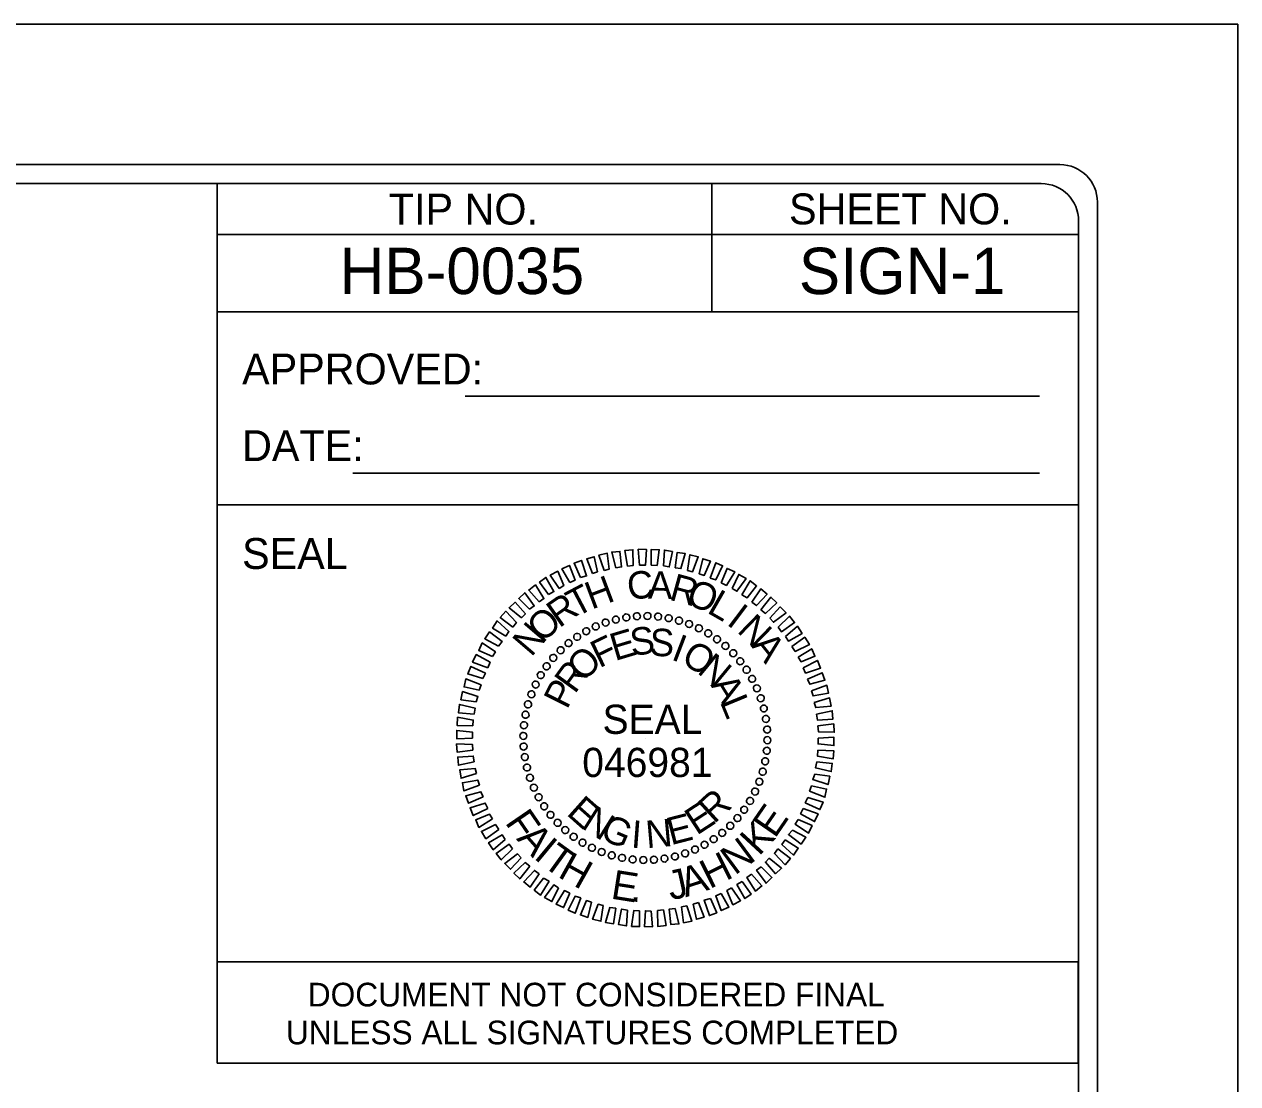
# Model space of a CAD drawing. Extents: x 1359317 to 1361345, y 1001522 to 1002524.
# Drawn here: x 1360569.7 to 1360865, y 1002265.9 to 1002523.7 of the extents above; entities that cross this region are included whole.
import ezdxf

# ---------------------------------------------------------------- set-up
doc = ezdxf.new("R2010")
doc.units = 0
for name, color, linetype in [('Sheet Data Field CELL', 7, 'Continuous'), ('Sheet PE Seal CELL', 7, 'Continuous'), ('Sheet Plot Border Outside CELL', 7, 'Continuous'), ('Sheet Title CELL', 7, 'Continuous'), ('Sheet_Title_CELL', 7, 'Continuous'), ('z - Construction', 7, 'Continuous')]:
    doc.layers.add(name, color=color, linetype=linetype)

msp = doc.modelspace()

# ---------------------------------------------------------------- linework, layer by layer
at = {"layer": 'Sheet PE Seal CELL'}
for p, q in [((1360708.79, 1002377.21), (1360708.79, 1002377.21)), ((1360711.16, 1002378.16), (1360711.16, 1002378.16)), ((1360713.64, 1002378.87), (1360713.64, 1002378.87)), ((1360716.25, 1002379.34), (1360716.25, 1002379.34)), ((1360718.79, 1002379.7), (1360718.79, 1002379.7)), ((1360721.4, 1002379.76), (1360721.4, 1002379.76)), ((1360724, 1002379.58), (1360724, 1002379.58)), ((1360726.55, 1002379.17), (1360726.55, 1002379.17)), ((1360729.04, 1002378.63), (1360729.04, 1002378.63)), ((1360731.52, 1002377.8), (1360731.52, 1002377.8)), ((1360704.23, 1002374.67), (1360704.23, 1002374.67)), ((1360706.48, 1002376.03), (1360706.48, 1002376.03)), ((1360733.89, 1002376.74), (1360733.89, 1002376.74)), ((1360736.2, 1002375.55), (1360736.2, 1002375.55)), ((1360700.2, 1002371.41), (1360700.2, 1002371.41)), ((1360702.15, 1002373.19), (1360702.15, 1002373.19)), ((1360738.33, 1002374.07), (1360738.33, 1002374.07)), ((1360740.41, 1002372.47), (1360740.41, 1002372.47)), ((1360698.42, 1002369.57), (1360698.42, 1002369.57)), ((1360742.24, 1002370.7), (1360742.24, 1002370.7)), ((1360744.02, 1002368.74), (1360744.02, 1002368.74)), ((1360696.83, 1002367.5), (1360696.83, 1002367.5)), ((1360745.5, 1002366.67), (1360745.5, 1002366.67)), ((1360694.16, 1002363.06), (1360694.16, 1002363.06)), ((1360695.34, 1002365.37), (1360695.34, 1002365.37)), ((1360746.86, 1002364.42), (1360746.86, 1002364.42)), ((1360693.09, 1002360.69), (1360693.09, 1002360.69)), ((1360748.05, 1002362.11), (1360748.05, 1002362.11)), ((1360748.99, 1002359.74), (1360748.99, 1002359.74)), ((1360692.27, 1002358.2), (1360692.27, 1002358.2)), ((1360749.7, 1002357.26), (1360749.7, 1002357.26)), ((1360691.73, 1002355.72), (1360691.73, 1002355.72)), ((1360750.18, 1002354.65), (1360750.18, 1002354.65)), ((1360691.32, 1002353.17), (1360691.32, 1002353.17)), ((1360750.53, 1002352.11), (1360750.53, 1002352.11)), ((1360691.14, 1002350.57), (1360691.14, 1002350.57)), ((1360691.2, 1002347.96), (1360691.2, 1002347.96)), ((1360720.87, 1002350.03), (1360720.87, 1002350.03)), ((1360750.59, 1002349.5), (1360750.59, 1002349.5)), ((1360691.56, 1002345.41), (1360691.56, 1002345.41)), ((1360750.41, 1002346.89), (1360750.41, 1002346.89)), ((1360692.03, 1002342.81), (1360692.03, 1002342.81)), ((1360749.47, 1002341.86), (1360749.47, 1002341.86)), ((1360750, 1002344.35), (1360750, 1002344.35)), ((1360692.74, 1002340.32), (1360692.74, 1002340.32)), ((1360748.64, 1002339.37), (1360748.64, 1002339.37)), ((1360693.69, 1002337.95), (1360693.69, 1002337.95)), ((1360747.57, 1002337.01), (1360747.57, 1002337.01)), ((1360694.87, 1002335.64), (1360694.87, 1002335.64)), ((1360696.23, 1002333.39), (1360696.23, 1002333.39)), ((1360746.39, 1002334.7), (1360746.39, 1002334.7)), ((1360697.71, 1002331.32), (1360697.71, 1002331.32)), ((1360743.31, 1002330.49), (1360743.31, 1002330.49)), ((1360744.91, 1002332.56), (1360744.91, 1002332.56)), ((1360699.49, 1002329.37), (1360699.49, 1002329.37)), ((1360701.33, 1002327.59), (1360701.33, 1002327.59)), ((1360741.53, 1002328.66), (1360741.53, 1002328.66)), ((1360703.4, 1002325.99), (1360703.4, 1002325.99)), ((1360705.53, 1002324.51), (1360705.53, 1002324.51)), ((1360737.51, 1002325.4), (1360737.51, 1002325.4)), ((1360739.58, 1002326.88), (1360739.58, 1002326.88)), ((1360707.84, 1002323.33), (1360707.84, 1002323.33)), ((1360710.21, 1002322.26), (1360710.21, 1002322.26)), ((1360712.69, 1002321.43), (1360712.69, 1002321.43)), ((1360728.09, 1002321.2), (1360728.09, 1002321.2)), ((1360730.58, 1002321.91), (1360730.58, 1002321.91)), ((1360732.95, 1002322.85), (1360732.95, 1002322.85)), ((1360735.26, 1002324.04), (1360735.26, 1002324.04)), ((1360715.18, 1002320.9), (1360715.18, 1002320.9)), ((1360717.73, 1002320.48), (1360717.73, 1002320.48)), ((1360720.33, 1002320.31), (1360720.33, 1002320.31)), ((1360722.94, 1002320.37), (1360722.94, 1002320.37)), ((1360725.48, 1002320.72), (1360725.48, 1002320.72))]:
    msp.add_line(p, q, dxfattribs=at)
for points in [[(1360710.8, 1002390.83), (1360709.56, 1002394.56), (1360711.57, 1002394.98), (1360712.04, 1002391.13)], [(1360713.64, 1002391.48), (1360712.69, 1002395.27), (1360714.65, 1002395.45), (1360715.06, 1002391.66)], [(1360716.48, 1002391.84), (1360715.83, 1002395.63), (1360717.85, 1002395.86), (1360717.91, 1002392.02)], [(1360719.44, 1002392.13), (1360719.15, 1002395.98), (1360721.1, 1002395.92), (1360720.87, 1002392.07)], [(1360722.29, 1002392.07), (1360722.29, 1002395.92), (1360724.24, 1002395.86), (1360723.71, 1002392.02)], [(1360725.25, 1002391.9), (1360725.48, 1002395.75), (1360727.44, 1002395.39), (1360726.67, 1002391.66)], [(1360728.09, 1002391.42), (1360728.62, 1002395.21), (1360730.58, 1002394.92), (1360729.51, 1002391.25)], [(1360702.45, 1002387.87), (1360700.56, 1002391.19), (1360702.39, 1002392.02), (1360703.75, 1002388.4)], [(1360705.06, 1002389.11), (1360703.52, 1002392.55), (1360705.29, 1002393.26), (1360706.54, 1002389.47)], [(1360707.96, 1002390.06), (1360706.6, 1002393.61), (1360708.43, 1002394.15), (1360709.2, 1002390.48)], [(1360731.11, 1002390.77), (1360731.7, 1002394.62), (1360733.72, 1002394.15), (1360732.35, 1002390.48)], [(1360733.95, 1002390), (1360734.84, 1002393.67), (1360736.68, 1002393.08), (1360735.2, 1002389.59)], [(1360736.62, 1002388.94), (1360737.98, 1002392.67), (1360739.64, 1002391.96), (1360737.98, 1002388.52)], [(1360697.3, 1002384.97), (1360695.11, 1002387.99), (1360696.65, 1002389.11), (1360698.6, 1002385.68)], [(1360699.9, 1002386.45), (1360697.71, 1002389.65), (1360699.55, 1002390.59), (1360701.03, 1002387.16)], [(1360739.28, 1002387.81), (1360740.76, 1002391.31), (1360742.6, 1002390.48), (1360740.58, 1002387.16)], [(1360742.01, 1002386.45), (1360743.6, 1002389.82), (1360745.38, 1002388.82), (1360743.13, 1002385.74)], [(1360695.05, 1002383.19), (1360692.5, 1002386.04), (1360694.1, 1002387.28), (1360696.17, 1002383.96)], [(1360744.31, 1002384.85), (1360746.39, 1002388.29), (1360747.93, 1002387.04), (1360745.62, 1002384.14)], [(1360746.74, 1002383.07), (1360748.93, 1002386.33), (1360750.47, 1002385.03), (1360747.87, 1002382.25)], [(1360692.68, 1002381.36), (1360690.07, 1002383.96), (1360691.5, 1002385.38), (1360693.81, 1002382.19)], [(1360748.99, 1002381.24), (1360751.42, 1002384.32), (1360752.84, 1002382.9), (1360750.12, 1002380.35)], [(1360688.65, 1002377.03), (1360685.57, 1002379.34), (1360686.88, 1002380.88), (1360689.48, 1002378.1)], [(1360690.73, 1002379.28), (1360687.71, 1002381.71), (1360689.19, 1002383.07), (1360691.67, 1002380.23)], [(1360751.12, 1002379.17), (1360753.67, 1002381.95), (1360755.09, 1002380.53), (1360752.01, 1002378.22)], [(1360686.88, 1002374.78), (1360683.68, 1002376.8), (1360684.8, 1002378.51), (1360687.65, 1002375.91)], [(1360753.2, 1002377.03), (1360755.92, 1002379.7), (1360757.16, 1002378.1), (1360754.03, 1002375.85)], [(1360754.97, 1002374.73), (1360757.88, 1002377.21), (1360759, 1002375.49), (1360755.68, 1002373.6)], [(1360685.1, 1002372.42), (1360681.78, 1002374.19), (1360682.97, 1002375.85), (1360686.05, 1002373.48)], [(1360756.51, 1002372.3), (1360759.65, 1002374.55), (1360760.78, 1002372.77), (1360757.34, 1002371.11)], [(1360683.68, 1002369.87), (1360680.3, 1002371.35), (1360681.19, 1002373.19), (1360684.39, 1002370.99)], [(1360758.05, 1002369.69), (1360761.37, 1002371.76), (1360762.14, 1002369.93), (1360758.76, 1002368.57)], [(1360682.5, 1002367.15), (1360678.82, 1002368.51), (1360679.71, 1002370.34), (1360683.09, 1002368.45)], [(1360759.24, 1002367.15), (1360762.73, 1002368.92), (1360763.5, 1002367.03), (1360759.83, 1002365.84)], [(1360681.31, 1002364.54), (1360677.64, 1002365.61), (1360678.41, 1002367.44), (1360681.96, 1002365.78)], [(1360760.3, 1002364.36), (1360763.91, 1002365.9), (1360764.57, 1002364.07), (1360760.89, 1002363.12)], [(1360680.42, 1002361.7), (1360676.75, 1002362.47), (1360677.17, 1002364.42), (1360680.9, 1002362.94)], [(1360761.25, 1002361.52), (1360765.04, 1002362.88), (1360765.4, 1002360.93), (1360761.66, 1002360.28)], [(1360679.65, 1002358.86), (1360675.98, 1002359.33), (1360676.4, 1002361.34), (1360680.13, 1002360.1)], [(1360761.96, 1002358.68), (1360765.69, 1002359.8), (1360766.05, 1002357.79), (1360762.32, 1002357.43)], [(1360679.18, 1002355.84), (1360675.39, 1002356.19), (1360675.63, 1002358.2), (1360679.48, 1002357.26)], [(1360762.49, 1002355.84), (1360766.34, 1002356.66), (1360766.52, 1002354.65), (1360762.73, 1002354.41)], [(1360678.88, 1002352.99), (1360675.03, 1002353.11), (1360675.15, 1002355.07), (1360679, 1002354.41)], [(1360678.82, 1002350.03), (1360674.98, 1002349.86), (1360674.98, 1002351.87), (1360678.82, 1002351.45)], [(1360762.85, 1002352.99), (1360766.7, 1002353.47), (1360766.82, 1002351.45), (1360762.97, 1002351.57)], [(1360678.88, 1002347.07), (1360675.03, 1002346.6), (1360674.92, 1002348.61), (1360678.76, 1002348.49)], [(1360762.91, 1002350.03), (1360766.76, 1002350.21), (1360766.76, 1002348.2), (1360762.91, 1002348.61)], [(1360679.24, 1002344.23), (1360675.39, 1002343.4), (1360675.21, 1002345.41), (1360679, 1002345.65)], [(1360762.85, 1002347.07), (1360766.7, 1002346.95), (1360766.58, 1002345), (1360762.73, 1002345.65)], [(1360679.77, 1002341.39), (1360676.04, 1002340.26), (1360675.69, 1002342.28), (1360679.42, 1002342.63)], [(1360762.55, 1002344.23), (1360766.34, 1002343.87), (1360766.11, 1002341.86), (1360762.26, 1002342.81)], [(1360680.48, 1002338.55), (1360676.69, 1002337.18), (1360676.34, 1002339.14), (1360680.07, 1002339.79)], [(1360762.08, 1002341.21), (1360765.75, 1002340.74), (1360765.34, 1002338.72), (1360761.61, 1002339.97)], [(1360681.43, 1002335.7), (1360677.82, 1002334.16), (1360677.17, 1002336), (1360680.84, 1002336.95)], [(1360761.31, 1002338.37), (1360764.98, 1002337.6), (1360764.57, 1002335.64), (1360760.84, 1002337.12)], [(1360682.5, 1002332.92), (1360679, 1002331.14), (1360678.23, 1002333.04), (1360681.9, 1002334.22)], [(1360759.24, 1002332.92), (1360762.91, 1002331.56), (1360762.02, 1002329.72), (1360758.64, 1002331.62)], [(1360760.42, 1002335.53), (1360764.09, 1002334.46), (1360763.32, 1002332.62), (1360759.77, 1002334.28)], [(1360683.68, 1002330.37), (1360680.36, 1002328.3), (1360679.59, 1002330.14), (1360682.97, 1002331.5)], [(1360758.05, 1002330.2), (1360761.43, 1002328.72), (1360760.54, 1002326.88), (1360757.34, 1002329.07)], [(1360685.22, 1002327.77), (1360682.08, 1002325.52), (1360680.96, 1002327.29), (1360684.39, 1002328.95)], [(1360756.63, 1002327.65), (1360759.95, 1002325.87), (1360758.76, 1002324.22), (1360755.68, 1002326.58)], [(1360686.76, 1002325.34), (1360683.86, 1002322.85), (1360682.73, 1002324.57), (1360686.05, 1002326.47)], [(1360688.54, 1002323.03), (1360685.81, 1002320.37), (1360684.57, 1002321.97), (1360687.71, 1002324.22)], [(1360754.86, 1002325.28), (1360758.05, 1002323.27), (1360756.93, 1002321.55), (1360754.09, 1002324.16)], [(1360690.61, 1002320.9), (1360688.06, 1002318.12), (1360686.64, 1002319.54), (1360689.72, 1002321.85)], [(1360753.08, 1002323.03), (1360756.16, 1002320.72), (1360754.86, 1002319.18), (1360752.25, 1002321.97)], [(1360692.74, 1002318.83), (1360690.31, 1002315.75), (1360688.89, 1002317.17), (1360691.61, 1002319.72)], [(1360749.05, 1002318.71), (1360751.66, 1002316.1), (1360750.24, 1002314.68), (1360747.93, 1002317.88)], [(1360751.01, 1002320.78), (1360754.03, 1002318.35), (1360752.55, 1002316.99), (1360750.06, 1002319.83)], [(1360694.99, 1002316.99), (1360692.8, 1002313.73), (1360691.26, 1002315.04), (1360693.86, 1002317.82)], [(1360697.42, 1002315.21), (1360695.34, 1002311.78), (1360693.81, 1002313.02), (1360696.11, 1002315.93)], [(1360746.68, 1002316.87), (1360749.23, 1002314.03), (1360747.63, 1002312.79), (1360745.56, 1002316.1)], [(1360699.73, 1002313.62), (1360698.13, 1002310.24), (1360696.35, 1002311.25), (1360698.6, 1002314.33)], [(1360702.45, 1002312.25), (1360700.97, 1002308.76), (1360699.13, 1002309.59), (1360701.15, 1002312.91)], [(1360741.83, 1002313.62), (1360744.02, 1002310.42), (1360742.18, 1002309.47), (1360740.7, 1002312.91)], [(1360744.43, 1002315.1), (1360746.62, 1002312.08), (1360745.08, 1002310.95), (1360743.13, 1002314.39)], [(1360705.12, 1002311.13), (1360703.75, 1002307.4), (1360702.1, 1002308.11), (1360703.75, 1002311.54)], [(1360707.78, 1002310.06), (1360706.89, 1002306.39), (1360705.06, 1002306.98), (1360706.54, 1002310.48)], [(1360710.62, 1002309.29), (1360710.03, 1002305.44), (1360708.02, 1002305.92), (1360709.38, 1002309.59)], [(1360733.77, 1002310), (1360735.14, 1002306.45), (1360733.3, 1002305.92), (1360732.53, 1002309.59)], [(1360736.68, 1002310.95), (1360738.22, 1002307.52), (1360736.44, 1002306.81), (1360735.2, 1002310.6)], [(1360739.28, 1002312.19), (1360741.18, 1002308.88), (1360739.34, 1002308.05), (1360737.98, 1002311.66)], [(1360713.64, 1002308.64), (1360713.11, 1002304.85), (1360711.16, 1002305.15), (1360712.22, 1002308.82)], [(1360716.48, 1002308.17), (1360716.25, 1002304.32), (1360714.29, 1002304.67), (1360715.06, 1002308.41)], [(1360719.44, 1002307.99), (1360719.44, 1002304.14), (1360717.49, 1002304.2), (1360718.02, 1002308.05)], [(1360722.29, 1002307.93), (1360722.58, 1002304.08), (1360720.63, 1002304.14), (1360720.87, 1002307.99)], [(1360725.25, 1002308.23), (1360725.9, 1002304.44), (1360723.89, 1002304.2), (1360723.83, 1002308.05)], [(1360728.09, 1002308.58), (1360729.04, 1002304.79), (1360727.08, 1002304.62), (1360726.67, 1002308.41)], [(1360730.93, 1002309.23), (1360732.18, 1002305.5), (1360730.16, 1002305.09), (1360729.69, 1002308.94)]]:
    msp.add_lwpolyline(points, close=True, dxfattribs=at)
for centre, major_axis in [((1360716.22, 1002379.37), (-0.133, 0.842)), ((1360718.79, 1002379.66), (-0.059, 0.851)), ((1360721.38, 1002379.73), (0.015, 0.853)), ((1360723.97, 1002379.57), (0.089, 0.848)), ((1360708.79, 1002377.17), (-0.347, 0.779)), ((1360711.2, 1002378.12), (-0.278, 0.806)), ((1360713.68, 1002378.85), (-0.206, 0.827)), ((1360726.53, 1002379.19), (0.163, 0.837)), ((1360729.05, 1002378.58), (0.235, 0.82)), ((1360731.51, 1002377.76), (0.306, 0.796)), ((1360733.89, 1002376.73), (0.374, 0.766)), ((1360704.26, 1002374.66), (-0.477, 0.707)), ((1360706.47, 1002376.01), (-0.413, 0.746)), ((1360736.16, 1002375.49), (0.439, 0.731)), ((1360738.32, 1002374.06), (0.501, 0.69)), ((1360700.23, 1002371.4), (-0.592, 0.613)), ((1360702.17, 1002373.12), (-0.537, 0.663)), ((1360740.35, 1002372.45), (0.559, 0.644)), ((1360742.23, 1002370.67), (0.613, 0.592)), ((1360696.84, 1002367.49), (-0.69, 0.501)), ((1360698.45, 1002369.52), (-0.644, 0.559)), ((1360743.95, 1002368.72), (0.663, 0.537)), ((1360695.41, 1002365.33), (-0.731, 0.439)), ((1360745.49, 1002366.64), (0.707, 0.477)), ((1360746.84, 1002364.43), (0.746, 0.413)), ((1360694.17, 1002363.05), (-0.766, 0.374)), ((1360748, 1002362.11), (0.779, 0.347)), ((1360693.14, 1002360.68), (-0.796, 0.306)), ((1360748.95, 1002359.7), (0.806, 0.278)), ((1360691.71, 1002355.7), (-0.837, 0.163)), ((1360692.31, 1002358.22), (-0.82, 0.235)), ((1360749.69, 1002357.22), (0.827, 0.206)), ((1360691.33, 1002353.14), (-0.848, 0.089)), ((1360750.2, 1002354.68), (0.842, 0.133)), ((1360691.17, 1002350.55), (-0.853, 0.015)), ((1360750.5, 1002352.1), (0.851, 0.059)), ((1360691.24, 1002347.96), (-0.851, -0.059)), ((1360750.41, 1002346.93), (0.848, -0.089)), ((1360750.56, 1002349.51), (0.853, -0.015)), ((1360691.53, 1002345.39), (-0.842, -0.133)), ((1360750.02, 1002344.37), (0.837, -0.163)), ((1360692.05, 1002342.85), (-0.827, -0.206)), ((1360749.42, 1002341.85), (0.82, -0.235)), ((1360692.78, 1002340.36), (-0.806, -0.278)), ((1360693.73, 1002337.95), (-0.779, -0.347)), ((1360748.6, 1002339.39), (0.796, -0.306)), ((1360694.89, 1002335.63), (-0.746, -0.413)), ((1360747.56, 1002337.01), (0.766, -0.374)), ((1360696.24, 1002333.42), (-0.707, -0.477)), ((1360744.9, 1002332.57), (0.69, -0.501)), ((1360746.33, 1002334.74), (0.731, -0.439)), ((1360697.78, 1002331.34), (-0.663, -0.537)), ((1360699.5, 1002329.4), (-0.613, -0.592)), ((1360743.28, 1002330.55), (0.644, -0.559)), ((1360701.38, 1002327.62), (-0.559, -0.644)), ((1360739.56, 1002326.95), (0.537, -0.663)), ((1360741.5, 1002328.67), (0.592, -0.613)), ((1360703.41, 1002326), (-0.501, -0.69)), ((1360705.57, 1002324.57), (-0.439, -0.731)), ((1360707.85, 1002323.34), (-0.374, -0.766)), ((1360735.27, 1002324.05), (0.413, -0.746)), ((1360737.48, 1002325.41), (0.477, -0.707)), ((1360710.22, 1002322.3), (-0.306, -0.796)), ((1360712.68, 1002321.48), (-0.235, -0.82)), ((1360715.2, 1002320.88), (-0.163, -0.837)), ((1360717.76, 1002320.49), (-0.089, -0.848)), ((1360720.35, 1002320.34), (-0.015, -0.853)), ((1360722.94, 1002320.4), (0.059, -0.851)), ((1360725.51, 1002320.7), (0.133, -0.842)), ((1360728.05, 1002321.21), (0.206, -0.827)), ((1360730.54, 1002321.95), (0.278, -0.806)), ((1360732.95, 1002322.9), (0.347, -0.779))]:
    msp.add_ellipse(centre, major_axis=major_axis, ratio=0.999708, dxfattribs=at)
at = {"layer": 'Sheet Plot Border Outside CELL'}
msp.add_lwpolyline([(1359316.74, 1002523.7), (1360865.01, 1002523.7), (1360865.01, 1001521.88), (1359316.74, 1001521.88)], close=True, dxfattribs=at)
at = {"layer": 'Sheet Title CELL'}
for p, q in [((1360616.64, 1002484.93), (1360616.64, 1002295.56)), ((1360737.05, 1002453.73), (1360737.05, 1002484.93)), ((1360616.64, 1002453.74), (1360616.64, 1002472.53)), ((1360616.64, 1002472.53), (1360737.05, 1002472.53)), ((1360737.05, 1002472.53), (1360826.38, 1002472.53)), ((1360826.38, 1002453.74), (1360616.64, 1002453.74)), ((1360685.54, 1002453.73), (1360644.83, 1002453.73)), ((1360616.64, 1002434.93), (1360616.64, 1002444.33)), ((1360677, 1002433.18), (1360816.78, 1002433.18)), ((1360616.64, 1002416.15), (1360616.64, 1002425.54)), ((1360649.71, 1002414.51), (1360816.78, 1002414.51)), ((1360616.64, 1002406.75), (1360818.6, 1002406.75)), ((1360616.64, 1002406.75), (1360826.38, 1002406.75)), ((1360616.64, 1002270.94), (1360616.64, 1002295.56)), ((1360616.64, 1002295.56), (1360826.2, 1002295.56)), ((1360826.38, 1002295.56), (1360616.64, 1002295.56)), ((1360826.2, 1002295.55), (1360826.2, 1002270.93)), ((1360826.2, 1002270.94), (1360616.64, 1002270.94))]:
    msp.add_line(p, q, dxfattribs=at)
at = {"layer": 'Sheet_Title_CELL'}
for p, q in [((1360821.75, 1002489.54), (1359360, 1002489.54)), ((1360817.19, 1002484.93), (1359410.09, 1002484.93)), ((1360830.86, 1001565.14), (1360830.86, 1002480.44)), ((1360826.3, 1001569.62), (1360826.3, 1002475.82))]:
    msp.add_line(p, q, dxfattribs=at)
for centre in [(1360821.75, 1002480.44), (1360817.19, 1002475.82)]:
    msp.add_arc(centre, 9.11, 0, 90, dxfattribs=at)
at = {"layer": 'z - Construction'}
for p, q in [((1360865.01, 1002523.7), (1359316.74, 1002523.7)), ((1360865.01, 1001521.88), (1360865.01, 1002523.7))]:
    msp.add_line(p, q, dxfattribs=at)

# ---------------------------------------------------------------- texts
at = {"layer": 'Sheet Data Field CELL'}
for s, height, p in [('TIP NO.', 7.518, (1360658.43, 1002474.97)), ('SHEET NO.', 7.518, (1360755.82, 1002475.01)), ('HB-0035', 11.277, (1360646.46, 1002458.05)), ('SIGN-1', 11.277, (1360758.2, 1002458.05)), ('APPROVED:', 7.518, (1360622.73, 1002436.07)), ('DATE:', 7.518, (1360622.73, 1002417.41)), ('SEAL', 7.518, (1360622.73, 1002391.17))]:
    msp.add_text(s, height=height, rotation=360, dxfattribs=at).set_placement(p)
at = {"layer": 'Sheet PE Seal CELL'}
for s, height, rotation, p in [('H', 6.68, 20.6195, (1360707.78, 1002381.24)), ('C', 6.68, 6.2199, (1360716.78, 1002383.61)), ('A', 6.68, 359.0203, (1360721.46, 1002383.96)), ('R', 6.68, 344.6211, (1360726.43, 1002383.73)), ('T', 6.68, 27.8198, (1360703.93, 1002379.28)), ('O', 6.68, 337.4212, (1360730.4, 1002382.84)), ('L', 6.68, 330.2209, (1360735.61, 1002380.65)), ('R', 6.68, 35.0205, (1360699.9, 1002376.68)), ('O', 6.68, 42.2217, (1360695.82, 1002373.01)), ('I', 6.68, 323.0201, (1360740.41, 1002377.8)), ('N', 6.68, 315.8189, (1360742.95, 1002375.97)), ('N', 6.68, 49.4235, (1360693.09, 1002369.57)), ('S', 6.68, 7.2556, (1360717.55, 1002369.99)), ('F', 6.68, 25.967, (1360709.67, 1002366.97)), ('E', 6.68, 16.6111, (1360713.46, 1002368.74)), ('S', 6.68, 357.9004, (1360721.81, 1002370.05)), ('I', 6.68, 339.1896, (1360726.91, 1002369.22)), ('A', 6.68, 308.6172, (1360746.45, 1002372.47)), ('O', 6.68, 44.6812, (1360705.77, 1002363.47)), ('O', 6.68, 329.8335, (1360729.27, 1002368.39)), ('R', 6.68, 54.0397, (1360703.69, 1002360.57)), ('N', 6.68, 320.4766, (1360733.24, 1002366.02)), ('P', 6.68, 63.3989, (1360701.8, 1002356.78)), ('A', 6.68, 301.7603, (1360736.62, 1002362.94)), ('L', 6.68, 292.4009, (1360738.93, 1002358.86)), ('E', 6.68, 318.2769, (1360701.44, 1002331.5)), ('R', 6.68, 42.4814, (1360737.56, 1002329.01)), ('N', 6.68, 327.634, (1360705, 1002328.3)), ('E', 6.68, 33.1241, (1360733.36, 1002326.23)), ('E', 7.1, 55.493, (1360752.37, 1002325.41)), ('F', 7.1, 304.4142, (1360686.56, 1002329.49)), ('G', 6.68, 336.9902, (1360709.5, 1002325.64)), ('I', 6.68, 355.7012, (1360717.25, 1002323.39)), ('N', 6.68, 5.0564, (1360721.22, 1002323.21)), ('E', 6.68, 14.4118, (1360727.08, 1002323.92)), ('K', 7.1, 47.2091, (1360748.49, 1002321.13)), ('A', 7.1, 311.4309, (1360689.33, 1002325.46)), ('I', 7.1, 320.2712, (1360693.48, 1002320.9)), ('T', 7.1, 324.0731, (1360695.47, 1002319.15)), ('N', 7.1, 36.4833, (1360742.63, 1002316.49)), ('H', 7.1, 330.8733, (1360699.3, 1002316.36)), ('H', 7.1, 26.4993, (1360736.49, 1002313.22)), ('J', 7.1, 12.4012, (1360727.05, 1002310.53)), ('A', 7.1, 17.659, (1360730.64, 1002311.26)), ('E', 7.1, 351.0577, (1360712.25, 1002310.99)), ('.', 7.1, 358.167, (1360717.15, 1002310.22))]:
    msp.add_text(s, height=height, rotation=rotation, dxfattribs=at).set_placement(p)
for s, p in [('SEAL', (1360710.45, 1002351.04)), ('046981', (1360705.5, 1002340.55))]:
    msp.add_text(s, height=7.104, dxfattribs=at).set_placement(p)
at = {"layer": 'Sheet Title CELL'}
for s, p in [('DOCUMENT NOT CONSIDERED FINAL', (1360638.71, 1002284.72)), ('UNLESS ALL SIGNATURES COMPLETED', (1360633.4, 1002275.5))]:
    msp.add_text(s, height=5.7619, rotation=360, dxfattribs=at).set_placement(p)

doc.saveas('drawing.dxf')
